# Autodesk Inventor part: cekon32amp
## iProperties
Created: 2005-11
Part Number: cekon32amp
Document SubType Name: Modeling
Designer: M.Reese
Author: M.Reese
Übersetzungsnorm: STEP AP214DIS
Dateiname: cekon32a.STEP
Vorprozessor: SolidWorks 2005074
Postprozessor: Build: 243, Release: 10 SP1 - Date: Mon 06/06/2005
Gesendete Einheiten: MILLIMETERS
Unbestimmtheit: 1e-05
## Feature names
1. Basis1
